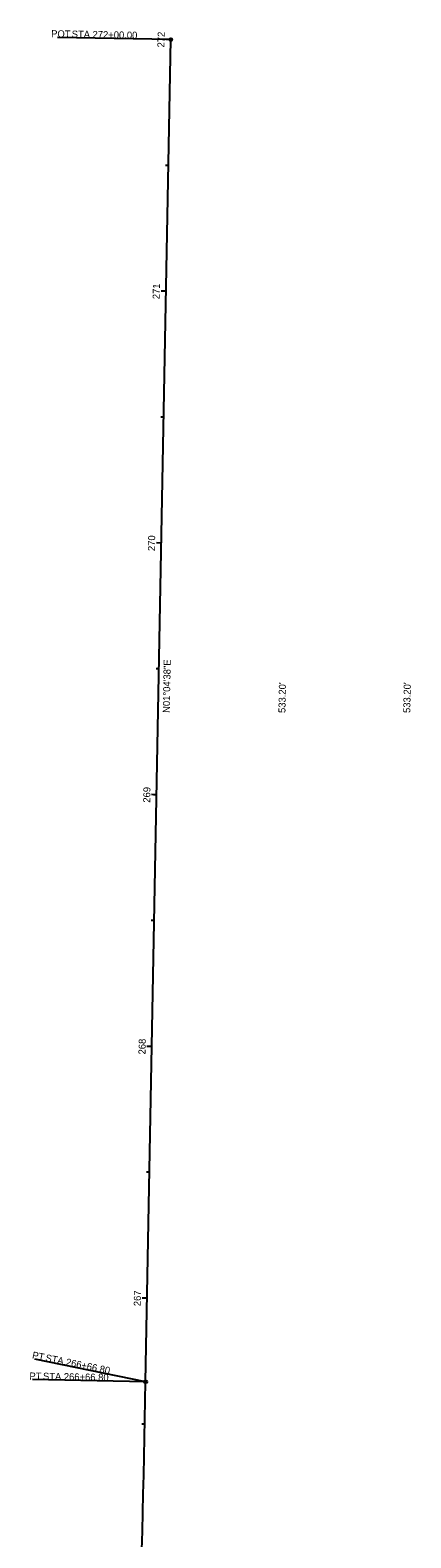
# Model space of a CAD drawing. Extents: x 1505540 to 1506187, y 327390 to 328596.
# Drawn here: x 1506036 to 1506187, y 327997 to 328596 of the extents above; entities that cross this region are included whole.
import ezdxf

# ---------------------------------------------------------------- set-up
doc = ezdxf.new("R2010")
doc.units = 0
for name, color, linetype in [('GE_X_Alignment', 7, 'Continuous'), ('GE_X_Alignment_100_Bearings', 7, 'Continuous'), ('GE_X_Alignment_100_Cardinal_Points', 7, 'Continuous'), ('GE_X_Alignment_100_Distances', 7, 'Continuous'), ('GE_X_Alignment_100_Stations', 7, 'Continuous'), ('GE_X_Alignment_500_Bearings', 7, 'Continuous'), ('GE_X_Alignment_500_Cardinal_Points', 7, 'Continuous'), ('GE_X_Alignment_500_Distances', 7, 'Continuous'), ('GE_X_Alignment_500_Stations', 7, 'Continuous')]:
    doc.layers.add(name, color=color, linetype=linetype)

msp = doc.modelspace()

# ---------------------------------------------------------------- linework, layer by layer
at = {"layer": 'GE_X_Alignment'}
msp.add_line((1506081.63, 328059.36), (1506091.65, 328592.47), dxfattribs=at)
msp.add_arc((1494624.5, 328274.78), 11459.16, 356.547823, 358.922822, dxfattribs=at)
at = {"layer": 'GE_X_Alignment_100_Cardinal_Points'}
for p, q in [((1506091.65, 328592.47), (1506046.66, 328593.31)), ((1506081.63, 328059.36), (1506037.55, 328068.4))]:
    msp.add_line(p, q, dxfattribs=at)
for centre in [(1506091.65, 328592.47), (1506081.63, 328059.36)]:
    msp.add_circle(centre, 0.6, dxfattribs=at)
at = {"layer": 'GE_X_Alignment_100_Stations'}
for p, q in [((1506091.65, 328592.47), (1506089.66, 328592.5)), ((1506090.71, 328542.48), (1506089.51, 328542.5)), ((1506089.77, 328492.48), (1506087.78, 328492.52)), ((1506088.83, 328442.49), (1506087.64, 328442.52)), ((1506087.89, 328392.5), (1506085.9, 328392.54)), ((1506086.95, 328342.51), (1506085.76, 328342.53)), ((1506086.01, 328292.52), (1506084.02, 328292.56)), ((1506085.08, 328242.53), (1506083.88, 328242.55)), ((1506084.14, 328192.54), (1506082.14, 328192.58)), ((1506083.2, 328142.55), (1506082, 328142.57)), ((1506082.26, 328092.56), (1506080.26, 328092.59)), ((1506081.3, 328042.56), (1506080.1, 328042.59))]:
    msp.add_line(p, q, dxfattribs=at)
at = {"layer": 'GE_X_Alignment_500_Cardinal_Points'}
for p, q in [((1506091.65, 328592.47), (1506046.66, 328593.31)), ((1506081.63, 328059.36), (1506036.64, 328060.21))]:
    msp.add_line(p, q, dxfattribs=at)
for centre in [(1506091.65, 328592.47), (1506081.63, 328059.36)]:
    msp.add_circle(centre, 0.6, dxfattribs=at)
at = {"layer": 'GE_X_Alignment_500_Stations'}
for p, q in [((1506091.65, 328592.47), (1506090.45, 328592.49)), ((1506089.77, 328492.48), (1506088.58, 328492.51)), ((1506087.89, 328392.5), (1506085.9, 328392.54)), ((1506086.01, 328292.52), (1506084.82, 328292.54)), ((1506084.14, 328192.54), (1506082.94, 328192.56)), ((1506082.26, 328092.56), (1506081.06, 328092.58))]:
    msp.add_line(p, q, dxfattribs=at)

# ---------------------------------------------------------------- texts
at = {"layer": 'GE_X_Alignment_100_Bearings'}
msp.add_text('N01°04\'38"E', height=2.8, rotation=88.92282, dxfattribs=at).set_placement((1506091.23, 328325))
at = {"layer": 'GE_X_Alignment_100_Cardinal_Points'}
for s, rotation, p in [('POT', 358.92282, (1506044.06, 328593.4)), (' STA. ', 358.92282, (1506051.19, 328593.26)), ('272+00.00', 358.92282, (1506060.51, 328593.09)), ('PT', 348.41374, (1506036.37, 328068.68)), (' STA. ', 348.41374, (1506040.63, 328067.8)), ('266+66.80', 348.41374, (1506049.76, 328065.93))]:
    msp.add_text(s, height=2.8, rotation=rotation, dxfattribs=at).set_placement(p)
at = {"layer": 'GE_X_Alignment_100_Distances'}
msp.add_text("533.20'", height=2.8, rotation=88.92282, dxfattribs=at).set_placement((1506137.18, 328324.97))
at = {"layer": 'GE_X_Alignment_100_Stations'}
for s, p in [('272', (1506089.09, 328589.3)), ('271', (1506087.21, 328489.31)), ('270', (1506085.33, 328389.28)), ('269', (1506083.45, 328289.34)), ('268', (1506081.57, 328189.34)), ('267', (1506079.69, 328089.36))]:
    msp.add_text(s, height=2.8, rotation=88.92282, dxfattribs=at).set_placement(p)
at = {"layer": 'GE_X_Alignment_500_Bearings'}
msp.add_text('N01°04\'38"E', height=2.8, rotation=88.92282, dxfattribs=at).set_placement((1506091.23, 328325))
at = {"layer": 'GE_X_Alignment_500_Cardinal_Points'}
for s, p in [('POT', (1506044.06, 328593.4)), (' STA. ', (1506051.19, 328593.26)), ('272+00.00', (1506060.51, 328593.09)), ('PT', (1506035.43, 328060.27)), (' STA. ', (1506039.78, 328060.18)), ('266+66.80', (1506049.1, 328060.01))]:
    msp.add_text(s, height=2.8, rotation=358.92282, dxfattribs=at).set_placement(p)
at = {"layer": 'GE_X_Alignment_500_Distances'}
msp.add_text("533.20'", height=2.8, rotation=88.92282, dxfattribs=at).set_placement((1506186.79, 328324.97))
at = {"layer": 'GE_X_Alignment_500_Stations'}
msp.add_text('270', height=2.8, rotation=88.92282, dxfattribs=at).set_placement((1506085.33, 328389.28))

doc.saveas('drawing.dxf')
